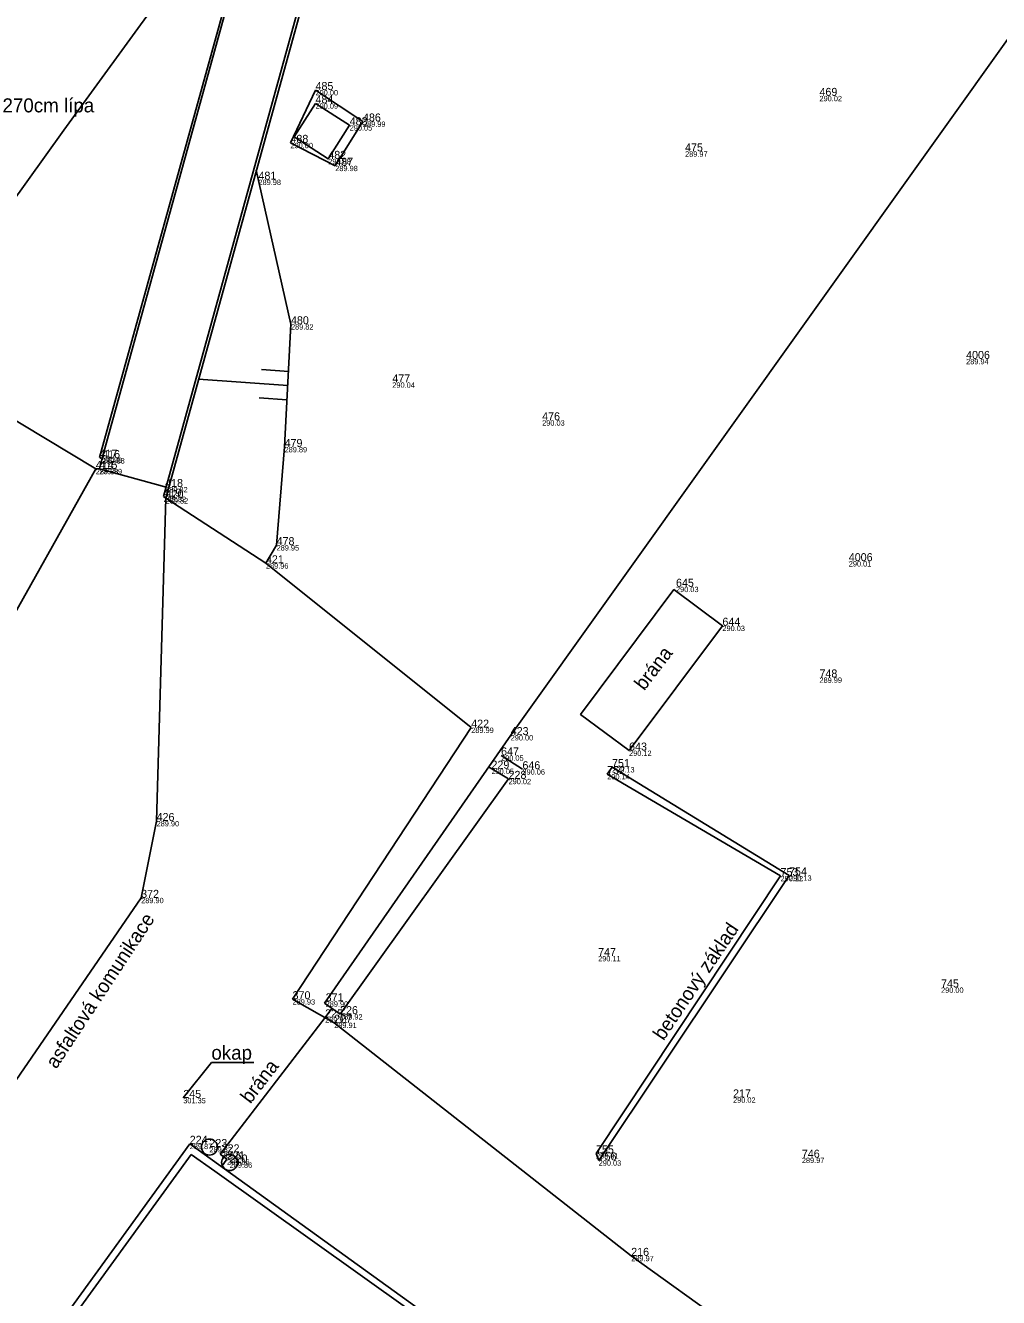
# Model space of a CAD drawing. Extents: x -805057 to -804930, y -994399 to -994240.
# Drawn here: x -805024.17 to -805005.92, y -994307.89 to -994284.05 of the extents above; entities that cross this region are included whole.
import ezdxf

# ---------------------------------------------------------------- set-up
doc = ezdxf.new("R2010")
doc.units = 0
for name, color, linetype in [('bod cislo', 7, 'Continuous'), ('bod pozice', 7, 'Continuous'), ('bod výška', 7, 'Continuous'), ('branka', 7, 'Continuous'), ('budova', 7, 'Continuous'), ('kamera', 7, 'Continuous'), ('Katastralni mapa', 7, 'Continuous'), ('komunikace', 7, 'Continuous'), ('plot', 7, 'Continuous'), ('popis', 7, 'Continuous'), ('svah', 7, 'Continuous'), ('svod', 7, 'Continuous'), ('šachta hranatá', 7, 'Continuous'), ('šrafy', 7, 'Continuous')]:
    doc.layers.add(name, color=color, linetype=linetype)

msp = doc.modelspace()

# ---------------------------------------------------------------- linework, layer by layer
at = {"layer": 'bod pozice'}
for p, q in [((-805018.73, -994285.26), (-805018.73, -994285.26)), ((-805009.28, -994285.37), (-805009.28, -994285.37)), ((-805018.73, -994285.51), (-805018.73, -994285.51)), ((-805017.84, -994285.85), (-805017.84, -994285.85)), ((-805018.09, -994285.92), (-805018.09, -994285.92)), ((-805019.2, -994286.25), (-805019.2, -994286.25)), ((-805018.49, -994286.55), (-805018.49, -994286.55)), ((-805011.8, -994286.41), (-805011.8, -994286.41)), ((-805018.36, -994286.68), (-805018.36, -994286.68)), ((-805019.8, -994286.94), (-805019.8, -994286.94)), ((-805019.19, -994289.65), (-805019.19, -994289.65)), ((-805006.53, -994290.3), (-805006.53, -994290.3)), ((-805017.29, -994290.74), (-805017.29, -994290.74)), ((-805014.48, -994291.45), (-805014.48, -994291.45)), ((-805019.31, -994291.95), (-805019.31, -994291.95)), ((-805022.78, -994292.15), (-805022.78, -994292.15)), ((-805022.73, -994292.16), (-805022.73, -994292.16)), ((-805022.85, -994292.36), (-805022.85, -994292.36)), ((-805022.78, -994292.36), (-805022.78, -994292.36)), ((-805021.55, -994292.7), (-805021.55, -994292.7)), ((-805021.58, -994292.88), (-805021.58, -994292.88)), ((-805021.54, -994292.91), (-805021.54, -994292.91)), ((-805019.46, -994293.79), (-805019.46, -994293.79)), ((-805019.66, -994294.13), (-805019.66, -994294.13)), ((-805008.73, -994294.09), (-805008.73, -994294.09)), ((-805011.97, -994294.57), (-805011.97, -994294.57)), ((-805011.1, -994295.3), (-805011.1, -994295.3)), ((-805009.28, -994296.27), (-805009.28, -994296.27)), ((-805015.81, -994297.21), (-805015.81, -994297.21)), ((-805015.07, -994297.35), (-805015.07, -994297.35)), ((-805015.25, -994297.73), (-805015.25, -994297.73)), ((-805012.85, -994297.64), (-805012.85, -994297.64)), ((-805015.43, -994297.98), (-805015.43, -994297.98)), ((-805014.85, -994297.99), (-805014.85, -994297.99)), ((-805013.17, -994297.95), (-805013.17, -994297.95)), ((-805015.11, -994298.17), (-805015.11, -994298.17)), ((-805013.26, -994298.08), (-805013.26, -994298.08)), ((-805021.71, -994298.96), (-805021.71, -994298.96)), ((-805010.01, -994299.99), (-805010.01, -994299.99)), ((-805009.85, -994299.98), (-805009.85, -994299.98)), ((-805022, -994300.4), (-805022, -994300.4)), ((-805013.43, -994301.49), (-805013.43, -994301.49)), ((-805007, -994302.08), (-805007, -994302.08)), ((-805019.16, -994302.3), (-805019.16, -994302.3)), ((-805018.54, -994302.34), (-805018.54, -994302.34)), ((-805018.27, -994302.58), (-805018.27, -994302.58)), ((-805018.55, -994302.64), (-805018.55, -994302.64)), ((-805018.38, -994302.74), (-805018.38, -994302.74)), ((-805021.21, -994304.15), (-805021.21, -994304.15)), ((-805010.9, -994304.14), (-805010.9, -994304.14)), ((-805021.089, -994305.009), (-805021.089, -994305.009)), ((-805020.72, -994305.07), (-805020.72, -994305.07)), ((-805020.49, -994305.17), (-805020.49, -994305.17)), ((-805013.47, -994305.19), (-805013.47, -994305.19)), ((-805020.39, -994305.3), (-805020.39, -994305.3)), ((-805020.34, -994305.36), (-805020.34, -994305.36)), ((-805013.42, -994305.32), (-805013.42, -994305.32)), ((-805009.61, -994305.27), (-805009.61, -994305.27)), ((-805012.81, -994307.11), (-805012.81, -994307.11))]:
    msp.add_line(p, q, dxfattribs=at)
at = {"layer": 'branka'}
msp.add_lwpolyline([(-805012.85, -994297.64), (-805011.1, -994295.3), (-805012.008, -994294.621), (-805013.758, -994296.961)], close=True, dxfattribs=at)
at = {"layer": 'budova'}
for p in [(-805026.92, -994313.06), (-805014.989, -994309.4)]:
    msp.add_line(p, (-805021.089, -994305.009), dxfattribs=at)
at = {"layer": 'kamera'}
msp.add_circle((-805020.34, -994305.36), 0.15, dxfattribs=at)
at = {"layer": 'Katastralni mapa'}
for points in [[(-805018.75, -994279.55), (-805023.45, -994286.01)], [(-805023.45, -994286.01), (-805026.2, -994289.84)], [(-805026.71, -994312.98), (-805021.06, -994305.21)], [(-805021.06, -994305.21), (-805020.62, -994305.52)], [(-805020.62, -994305.52), (-805015.17, -994309.41)]]:
    msp.add_lwpolyline(points, dxfattribs=at)
at = {"layer": 'komunikace'}
for p, q in [((-805022.78, -994292.15), (-805019.48, -994280.24)), ((-805019.44, -994280.24), (-805022.73, -994292.16)), ((-805021.58, -994292.88), (-805018.17, -994280.54)), ((-805018.12, -994280.55), (-805021.54, -994292.91)), ((-805019.2, -994286.25), (-805018.73, -994285.26)), ((-805018.73, -994285.26), (-805017.84, -994285.85)), ((-805017.84, -994285.85), (-805018.36, -994286.68)), ((-805018.36, -994286.68), (-805019.2, -994286.25)), ((-805029.24, -994288.52), (-805022.85, -994292.36)), ((-805022.73, -994292.16), (-805022.78, -994292.15)), ((-805022.78, -994292.36), (-805022.73, -994292.16)), ((-805025.76, -994297.54), (-805022.85, -994292.36)), ((-805022.85, -994292.36), (-805022.78, -994292.36)), ((-805022.78, -994292.36), (-805021.532, -994292.705)), ((-805021.71, -994298.96), (-805021.54, -994292.91)), ((-805021.58, -994292.88), (-805021.54, -994292.91)), ((-805019.66, -994294.13), (-805021.54, -994292.91)), ((-805015.81, -994297.21), (-805019.66, -994294.13)), ((-805019.16, -994302.3), (-805015.81, -994297.21)), ((-805013.26, -994298.08), (-805013.17, -994297.95)), ((-805013.17, -994297.95), (-805009.85, -994299.98)), ((-805010.01, -994299.99), (-805013.26, -994298.08)), ((-805021.71, -994298.96), (-805022, -994300.4)), ((-805013.47, -994305.19), (-805010.01, -994299.99)), ((-805009.85, -994299.98), (-805013.42, -994305.32)), ((-805028.28, -994309.54), (-805022, -994300.4)), ((-805018.38, -994302.74), (-805019.16, -994302.3)), ((-805012.81, -994307.11), (-805018.38, -994302.74)), ((-805013.42, -994305.32), (-805013.47, -994305.19)), ((-805006.16, -994311.87), (-805012.81, -994307.11))]:
    msp.add_line(p, q, dxfattribs=at)
at = {"layer": 'plot'}
for p, q in [((-805002.96, -994280.4), (-805015.07, -994297.35)), ((-805018.562, -994302.371), (-805015.07, -994297.35)), ((-805014.85, -994297.99), (-805015.25, -994297.73)), ((-805015.11, -994298.17), (-805015.485, -994297.947)), ((-805015.11, -994298.17), (-805018.27, -994302.58)), ((-805018.27, -994302.58), (-805018.562, -994302.371)), ((-805018.421, -994302.472), (-805018.55, -994302.64)), ((-805020.515, -994305.202), (-805018.55, -994302.64)), ((-805020.39, -994305.3), (-805020.515, -994305.202)), ((-805020.39, -994305.3), (-805020.491, -994305.439))]:
    msp.add_line(p, q, dxfattribs=at)
at = {"layer": 'popis'}
for q in [(-805021.21, -994304.15), (-805019.884, -994303.486)]:
    msp.add_line((-805020.683, -994303.486), q, dxfattribs=at)
at = {"layer": 'svah'}
for p, q in [((-805019.84, -994286.764), (-805019.19, -994289.65)), ((-805019.19, -994289.65), (-805019.31, -994291.95)), ((-805019.31, -994291.95), (-805019.46, -994293.79)), ((-805019.46, -994293.79), (-805019.66, -994294.13))]:
    msp.add_line(p, q, dxfattribs=at)
at = {"layer": 'svod'}
msp.add_circle((-805020.72, -994305.07), 0.15, dxfattribs=at)
at = {"layer": 'šachta hranatá'}
msp.add_lwpolyline([(-805018.73, -994285.51), (-805018.09, -994285.92), (-805018.491, -994286.549), (-805019.131, -994286.139)], close=True, dxfattribs=at)
at = {"layer": 'šrafy'}
for p, q in [((-805019.231, -994290.534), (-805019.745, -994290.497)), ((-805019.25, -994290.8), (-805020.923, -994290.68)), ((-805019.269, -994291.067), (-805019.784, -994291.03))]:
    msp.add_line(p, q, dxfattribs=at)

# ---------------------------------------------------------------- texts
at = {"layer": 'bod cislo'}
for s, p in [('485    ', (-805018.73, -994285.26)), ('484    ', (-805018.73, -994285.51)), ('469    ', (-805009.28, -994285.37)), ('483    ', (-805018.09, -994285.92)), ('486    ', (-805017.84, -994285.85)), ('488    ', (-805019.2, -994286.25)), ('475    ', (-805011.8, -994286.41)), ('482    ', (-805018.49, -994286.55)), ('487    ', (-805018.36, -994286.68)), ('481    ', (-805019.8, -994286.94)), ('480    ', (-805019.19, -994289.65)), ('4006    ', (-805006.53, -994290.3)), ('477    ', (-805017.29, -994290.74)), ('476    ', (-805014.48, -994291.45)), ('479    ', (-805019.31, -994291.95)), ('417    ', (-805022.78, -994292.15)), ('416    ', (-805022.73, -994292.16)), ('414    ', (-805022.85, -994292.36)), ('415    ', (-805022.78, -994292.36)), ('418    ', (-805021.55, -994292.7)), ('419    ', (-805021.58, -994292.88)), ('420    ', (-805021.54, -994292.91)), ('478    ', (-805019.46, -994293.79)), ('421    ', (-805019.66, -994294.13)), ('4006    ', (-805008.73, -994294.09)), ('645    ', (-805011.97, -994294.57)), ('644    ', (-805011.1, -994295.3)), ('748    ', (-805009.28, -994296.27)), ('422    ', (-805015.81, -994297.21)), ('423    ', (-805015.07, -994297.35)), ('647    ', (-805015.25, -994297.73)), ('643    ', (-805012.85, -994297.64)), ('751    ', (-805013.17, -994297.95)), ('229    ', (-805015.43, -994297.98)), ('228    ', (-805015.11, -994298.17)), ('646    ', (-805014.85, -994297.99)), ('752    ', (-805013.26, -994298.08)), ('426    ', (-805021.71, -994298.96)), ('753    ', (-805010.01, -994299.99)), ('754    ', (-805009.85, -994299.98)), ('372    ', (-805022, -994300.4)), ('747    ', (-805013.43, -994301.49)), ('745    ', (-805007, -994302.08)), ('370    ', (-805019.16, -994302.3)), ('371    ', (-805018.54, -994302.34)), ('225    ', (-805018.55, -994302.64)), ('227    ', (-805018.38, -994302.74)), ('226    ', (-805018.27, -994302.58)), ('245    ', (-805021.21, -994304.15)), ('217    ', (-805010.9, -994304.14)), ('224    ', (-805021.089, -994305.009)), ('223    ', (-805020.72, -994305.07)), ('222    ', (-805020.49, -994305.17)), ('221    ', (-805020.39, -994305.3)), ('220    ', (-805020.34, -994305.36)), ('755    ', (-805013.47, -994305.19)), ('756    ', (-805013.42, -994305.32)), ('746    ', (-805009.61, -994305.27)), ('216    ', (-805012.81, -994307.11))]:
    msp.add_text(s, height=0.15, dxfattribs=at).set_placement(p)
at = {"layer": 'bod výška'}
for s, p in [('290.00  ', (-805018.73, -994285.36)), ('290.02  ', (-805009.28, -994285.47)), ('290.09  ', (-805018.73, -994285.61)), ('289.99  ', (-805017.84, -994285.95)), ('290.05  ', (-805018.09, -994286.02)), ('290.00  ', (-805019.2, -994286.35)), ('290.08  ', (-805018.49, -994286.65)), ('289.97  ', (-805011.8, -994286.51)), ('289.98  ', (-805018.36, -994286.78)), ('289.98  ', (-805019.8, -994287.04)), ('289.82  ', (-805019.19, -994289.75)), ('289.94  ', (-805006.53, -994290.4)), ('290.04  ', (-805017.29, -994290.84)), ('290.03  ', (-805014.48, -994291.55)), ('289.89  ', (-805019.31, -994292.05)), ('289.88  ', (-805022.78, -994292.25)), ('289.88  ', (-805022.73, -994292.26)), ('289.88  ', (-805022.85, -994292.46)), ('289.89  ', (-805022.78, -994292.46)), ('289.82  ', (-805021.55, -994292.8)), ('289.82  ', (-805021.58, -994292.98)), ('289.82  ', (-805021.54, -994293.01)), ('289.95  ', (-805019.46, -994293.89)), ('289.96  ', (-805019.66, -994294.23)), ('290.01  ', (-805008.73, -994294.19)), ('290.03  ', (-805011.97, -994294.67)), ('290.03  ', (-805011.1, -994295.4)), ('289.99  ', (-805009.28, -994296.37)), ('289.99  ', (-805015.81, -994297.31)), ('290.00  ', (-805015.07, -994297.45)), ('290.05  ', (-805015.25, -994297.83)), ('290.12  ', (-805012.85, -994297.74)), ('290.05  ', (-805015.43, -994298.08)), ('290.06  ', (-805014.85, -994298.09)), ('290.13  ', (-805013.17, -994298.05)), ('290.02  ', (-805015.11, -994298.27)), ('290.14  ', (-805013.26, -994298.18)), ('289.90  ', (-805021.71, -994299.06)), ('290.12  ', (-805010.01, -994300.09)), ('290.13  ', (-805009.85, -994300.08)), ('289.90  ', (-805022, -994300.5)), ('290.11  ', (-805013.43, -994301.59)), ('290.00  ', (-805007, -994302.18)), ('289.93  ', (-805019.16, -994302.4)), ('289.90  ', (-805018.54, -994302.44)), ('289.92  ', (-805018.27, -994302.68)), ('289.91  ', (-805018.55, -994302.74)), ('289.91  ', (-805018.38, -994302.84)), ('301.35  ', (-805021.21, -994304.25)), ('290.02  ', (-805010.9, -994304.24)), ('289.87  ', (-805021.089, -994305.109)), ('289.82  ', (-805020.72, -994305.17)), ('289.81  ', (-805020.49, -994305.27)), ('290.01  ', (-805013.47, -994305.29)), ('289.86  ', (-805020.39, -994305.4)), ('289.86  ', (-805020.34, -994305.46)), ('290.03  ', (-805013.42, -994305.42)), ('289.97  ', (-805009.61, -994305.37)), ('289.97  ', (-805012.81, -994307.21))]:
    msp.add_text(s, height=0.1, dxfattribs=at).set_placement(p)
at = {"layer": 'popis'}
for s, p in [('270cm lípa', (-805024.6, -994285.679)), ('okap', (-805020.683, -994303.433))]:
    msp.add_text(s, height=0.2629, dxfattribs=at).set_placement(p)
for s, height, rotation, p in [('brána', 0.2629, 52.5685, (-805012.566, -994296.53)), ('asfaltová komunikace', 0.26289, 56.6946, (-805023.591, -994303.62)), ('betonový základ', 0.26289, 55.9904, (-805012.204, -994303.089)), ('brána', 0.2629, 52.5685, (-805019.952, -994304.273))]:
    msp.add_text(s, height=height, rotation=rotation, dxfattribs=at).set_placement(p)

doc.saveas('drawing.dxf')
